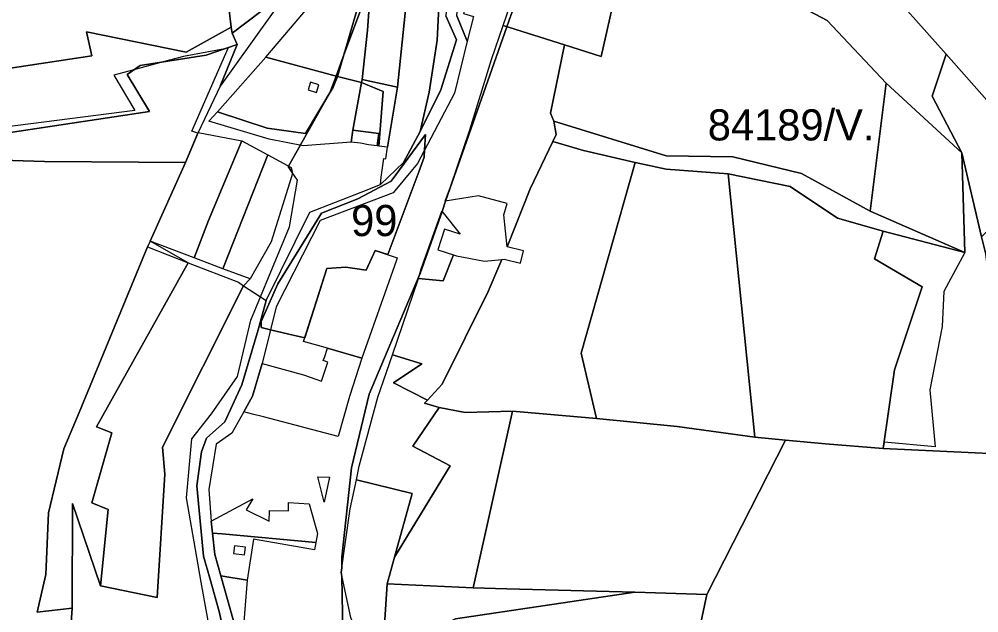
# Model space of a CAD drawing. Extents: x -477304 to -465429, y -1159113 to -1149210.
# Drawn here: x -475656.6 to -475194.4, y -1153026.8 to -1152741 of the extents above; entities that cross this region are included whole.
import ezdxf

# ---------------------------------------------------------------- set-up
doc = ezdxf.new("R2010")
doc.units = 0
for name, color, linetype in [('BPEJ_s', 7, 'Continuous'), ('orna_s', 7, 'Continuous'), ('PUPFL_s', 7, 'Continuous'), ('trav_porost_s', 7, 'Continuous'), ('voda_s', 7, 'Continuous'), ('zahrada_s', 7, 'Continuous')]:
    doc.layers.add(name, color=color, linetype=linetype)

msp = doc.modelspace()

# ---------------------------------------------------------------- linework, layer by layer
at = {"layer": 'BPEJ_s'}
for points in [[(-475500.81, -1153036.32), (-475501.16, -1153009.29), (-475501.54, -1153007.49), (-475501.21, -1153005.16), (-475501.28, -1153000), (-475496.5, -1152957), (-475488, -1152921.5), (-475464.1, -1152864.93), (-475463.5, -1152863.5), (-475452.96, -1152833.54), (-475451.22, -1152828.6), (-475421.69, -1152744.68), (-475407.14, -1152703.33)], [(-475407.14, -1152703.33), (-475421.69, -1152744.68), (-475451.22, -1152828.6), (-475452.96, -1152833.54), (-475463.5, -1152863.5), (-475464.1, -1152864.93), (-475488, -1152921.5), (-475496.5, -1152957), (-475501.28, -1153000), (-475501.21, -1153005.16)], [(-475489.77, -1152730.19), (-475500.69, -1152759.54), (-475504, -1152768.43), (-475507, -1152776.5), (-475507.3, -1152777.03), (-475521.24, -1152801.78), (-475526.88, -1152811.78), (-475527, -1152812), (-475525.07, -1152814.79), (-475524.91, -1152815.39), (-475535.25, -1152848.29), (-475545.44, -1152866.11), (-475548.51, -1152869.36), (-475587.54, -1152947.04), (-475586.48, -1152960.09), (-475590.2, -1153019.39), (-475617.49, -1153013.79), (-475613.73, -1152977.13), (-475621.62, -1152973.88), (-475611.96, -1152940.26), (-475619.33, -1152937.28), (-475575.21, -1152858.31), (-475593.59, -1152847.84), (-475576.52, -1152809.97), (-475570.52, -1152795.86), (-475573.5, -1152795), (-475556, -1152755), (-475557.53, -1152755.29), (-475577.5, -1152759), (-475587.33, -1152761.64), (-475601.43, -1152765.43), (-475611, -1152768), (-475601, -1152785), (-475688.7, -1152796.2)], [(-475563.53, -1153042.27), (-475569, -1153012), (-475571.07, -1153000), (-475576, -1152971.5), (-475573.5, -1152943), (-475564, -1152931), (-475551.5, -1152913), (-475545, -1152886), (-475540.37, -1152874.73), (-475526.5, -1152841), (-475522.5, -1152818.5), (-475525.07, -1152814.79), (-475527, -1152812), (-475526.88, -1152811.78), (-475521.24, -1152801.78), (-475507.3, -1152777.03), (-475507, -1152776.5), (-475504, -1152768.43), (-475500.69, -1152759.54), (-475489.77, -1152730.19)], [(-475279.36, -1152735.39), (-475267.5, -1152741.66), (-475238.97, -1152771.86), (-475202.55, -1152805.3), (-475201.18, -1152853.32), (-475211.2, -1152872.11), (-475212, -1152889), (-475218, -1152919.5), (-475215.5, -1152947), (-475240.05, -1152944.74), (-475240.48, -1152947.68), (-475268.28, -1152945.55), (-475287.45, -1152943.72), (-475325.37, -1153017.96), (-475330.61, -1153042.24)], [(-475279.36, -1152735.39), (-475267.5, -1152741.66), (-475238.97, -1152771.86), (-475202.55, -1152805.3), (-475201.18, -1152853.32), (-475211.2, -1152872.11), (-475212, -1152889), (-475218, -1152919.5), (-475215.5, -1152947), (-475240.05, -1152944.74), (-475240.48, -1152947.68), (-475268.28, -1152945.55), (-475287.45, -1152943.72), (-475325.37, -1153017.96), (-475330.61, -1153042.24)], [(-475524.91, -1152815.39), (-475535.25, -1152848.29), (-475545.44, -1152866.11), (-475548.51, -1152869.36), (-475587.54, -1152947.04), (-475586.48, -1152960.09), (-475590.2, -1153019.39), (-475617.49, -1153013.79), (-475613.73, -1152977.13), (-475621.62, -1152973.88), (-475611.96, -1152940.26), (-475619.33, -1152937.28), (-475575.21, -1152858.31), (-475593.59, -1152847.84), (-475576.52, -1152809.97), (-475570.52, -1152795.86), (-475573.5, -1152795), (-475556, -1152755), (-475557.53, -1152755.29), (-475577.5, -1152759), (-475587.33, -1152761.64), (-475601.43, -1152765.43), (-475611, -1152768), (-475601, -1152785), (-475688.7, -1152796.2)], [(-475563.53, -1153042.27), (-475569, -1153012), (-475571.07, -1153000), (-475576, -1152971.5), (-475573.5, -1152943), (-475564, -1152931), (-475551.5, -1152913), (-475545, -1152886), (-475540.37, -1152874.73), (-475526.5, -1152841), (-475522.5, -1152818.5), (-475525.07, -1152814.79), (-475524.91, -1152815.39)], [(-475501.21, -1153005.16), (-475501.54, -1153007.49), (-475501.16, -1153009.29), (-475500.81, -1153036.32)]]:
    msp.add_lwpolyline(points, dxfattribs=at)
for points in [[(-475464.14, -1152814.54), (-475479.09, -1152854.4), (-475485.14, -1152852.33), (-475489.52, -1152861.83), (-475499.35, -1152860.35), (-475508.44, -1152861.13), (-475519.11, -1152894.42), (-475526.82, -1152892.6), (-475535.6, -1152890.53), (-475540, -1152889.5), (-475540, -1152886.5), (-475532, -1152868.5), (-475511, -1152834.5), (-475493.5, -1152827.5), (-475477.5, -1152819), (-475461, -1152796.5), (-475461.34, -1152803.9), (-475461.5, -1152807.5), (-475462.83, -1152811.05)], [(-475464.14, -1152814.54), (-475462.83, -1152811.05), (-475461.5, -1152807.5), (-475461.34, -1152803.9), (-475461, -1152796.5), (-475477.5, -1152819), (-475493.5, -1152827.5), (-475511, -1152834.5), (-475532, -1152868.5), (-475540, -1152886.5), (-475540, -1152889.5), (-475535.6, -1152890.53), (-475526.82, -1152892.6), (-475519.11, -1152894.42), (-475508.44, -1152861.13), (-475499.35, -1152860.35), (-475489.52, -1152861.83), (-475485.14, -1152852.33), (-475479.09, -1152854.4)]]:
    msp.add_lwpolyline(points, close=True, dxfattribs=at)
at = {"layer": 'orna_s'}
for points in [[(-475474.41, -1152773.74), (-475470.29, -1152733.49), (-475466.26, -1152707.82), (-475459.33, -1152709.97), (-475453.25, -1152709.43), (-475455.35, -1152751.18), (-475459.14, -1152776.1), (-475463.5, -1152795.08), (-475471.52, -1152809.95), (-475482.63, -1152820.63), (-475482.23, -1152817.05), (-475481.05, -1152808.1), (-475480.01, -1152808.24), (-475479.28, -1152802.69)], [(-475492.49, -1152731.72), (-475503.36, -1152768.6), (-475537.87, -1152759.39), (-475508.67, -1152724.8), (-475503.55, -1152727.41)], [(-475488.91, -1152746.29), (-475487.74, -1152730.6), (-475483.62, -1152731.43), (-475470.29, -1152733.49), (-475474.41, -1152773.74), (-475491.45, -1152770.14)], [(-475537.87, -1152759.39), (-475503.36, -1152768.6), (-475505.33, -1152773.76), (-475518.78, -1152796.1), (-475537.26, -1152793.53), (-475561.15, -1152785.65)], [(-475516.28, -1152771.43), (-475517.38, -1152775.02), (-475513.35, -1152776.25), (-475512.25, -1152772.66)], [(-475593.59, -1152847.84), (-475576.52, -1152809.97), (-475570.41, -1152795.61), (-475549.31, -1152799.53), (-475565.52, -1152837.98), (-475572.32, -1152855.91)]]:
    msp.add_lwpolyline(points, close=True, dxfattribs=at)
at = {"layer": 'PUPFL_s'}
for points in [[(-475305.99, -1152727.63), (-475302.35, -1152706.82), (-475273.91, -1152717.63), (-475251.75, -1152720.8), (-475243.34, -1152720.48), (-475210.2, -1152757.89), (-475216.87, -1152778.07), (-475202.55, -1152805.3), (-475238.97, -1152771.86), (-475267.5, -1152741.66), (-475279.36, -1152735.39)], [(-475688.75, -1152784.73), (-475693.19, -1152770.91), (-475686.56, -1152768.49), (-475621.57, -1152758.65), (-475624.23, -1152747.16), (-475576.16, -1152756.87), (-475554.46, -1152744.91), (-475554.12, -1152747.68), (-475551.6, -1152753.22), (-475566.51, -1152758.41), (-475598.28, -1152763.34), (-475604.67, -1152767.58), (-475593.82, -1152785.42), (-475688.69, -1152799.79)], [(-475694.55, -1152800.67), (-475688.69, -1152799.79), (-475593.82, -1152785.42), (-475604.67, -1152767.58), (-475598.28, -1152763.34), (-475566.51, -1152758.41), (-475551.6, -1152753.22), (-475559.87, -1152773.35), (-475570.41, -1152795.61), (-475576.52, -1152809.97), (-475644.5, -1152809.53), (-475700.83, -1152807.76), (-475694.32, -1152806.09)], [(-475193.07, -1152845.82), (-475202.55, -1152805.3), (-475216.87, -1152778.07), (-475210.2, -1152757.89), (-475161.18, -1152813.24)], [(-475240.42, -1152843.05), (-475201.18, -1152853.32), (-475202.55, -1152805.3), (-475193.07, -1152845.82), (-475190.97, -1152854.13), (-475184.7, -1152902.6), (-475185.82, -1152950.28), (-475240.48, -1152947.68), (-475234.99, -1152909.87), (-475221.7, -1152869.94), (-475244.73, -1152856.39)], [(-475154.57, -1152960.71), (-475188.25, -1153073.92), (-475205.9, -1153072.04), (-475319.2, -1153107.9), (-475350.51, -1153121.3), (-475347.24, -1153109.36), (-475336.52, -1153070.18), (-475330.61, -1153042.24), (-475325.37, -1153017.96), (-475287.45, -1152943.72), (-475268.28, -1152945.55), (-475240.48, -1152947.68), (-475185.82, -1152950.28), (-475184.7, -1152902.6), (-475190.97, -1152854.13), (-475193.07, -1152845.82), (-475161.18, -1152813.24), (-475126.45, -1152850.38), (-475138.02, -1152881.46), (-475143.48, -1152923), (-475153.28, -1152956.92)], [(-475575.21, -1152858.31), (-475619.33, -1152937.28), (-475611.96, -1152940.26), (-475621.62, -1152973.88), (-475613.73, -1152977.13), (-475617.49, -1153013.79), (-475630.92, -1152974.27), (-475631.11, -1153024.55), (-475648.02, -1153026.57), (-475643.82, -1153008.41), (-475642.55, -1152978.65), (-475635.17, -1152947.89), (-475627.73, -1152930.46), (-475594.83, -1152850.7)]]:
    msp.add_lwpolyline(points, close=True, dxfattribs=at)
for points in [[(-475161.18, -1152813.24), (-475210.2, -1152757.89), (-475243.34, -1152720.48)], [(-475700.83, -1152807.76), (-475644.5, -1152809.53), (-475576.52, -1152809.97), (-475593.59, -1152847.84), (-475594.83, -1152850.7), (-475627.73, -1152930.46), (-475635.17, -1152947.89), (-475642.55, -1152978.65), (-475643.82, -1153008.41), (-475648.02, -1153026.57), (-475631.11, -1153024.55), (-475635.36, -1153085.02), (-475662.21, -1153095.67)], [(-475635.36, -1153085.02), (-475631.11, -1153024.55), (-475630.92, -1152974.27), (-475617.49, -1153013.79), (-475590.2, -1153019.39), (-475586.48, -1152960.09), (-475587.54, -1152947.04), (-475548.51, -1152869.36), (-475537.64, -1152876.53), (-475541.47, -1152890.66), (-475549.36, -1152917.02), (-475557.61, -1152934.96), (-475566.47, -1152942.81), (-475568.81, -1152949.28), (-475571.1, -1152965.73), (-475567.92, -1152999.53), (-475564.76, -1153010.23), (-475560.24, -1153026.23), (-475557.79, -1153037.72)]]:
    msp.add_lwpolyline(points, dxfattribs=at)
at = {"layer": 'trav_porost_s'}
for points in [[(-475556.79, -1152726.11), (-475563.59, -1152714.27), (-475568.62, -1152709.29), (-475579.41, -1152701.49), (-475574.39, -1152690.12), (-475561.12, -1152693.94), (-475549.78, -1152702.51), (-475547.62, -1152704.31), (-475539.13, -1152723.9), (-475540.16, -1152737.25), (-475554.12, -1152747.68), (-475554.46, -1152744.91)], [(-475563.59, -1152714.27), (-475556.79, -1152726.11), (-475554.46, -1152744.91), (-475576.16, -1152756.87), (-475624.23, -1152747.16), (-475621.57, -1152758.65), (-475686.56, -1152768.49), (-475695.79, -1152741.11), (-475675.66, -1152712.58), (-475642.36, -1152708.05), (-475639.99, -1152696.96), (-475614.53, -1152691.15), (-475585.75, -1152697.58), (-475579.41, -1152701.49), (-475568.62, -1152709.29)], [(-475554.12, -1152747.68), (-475540.16, -1152737.25), (-475539.13, -1152723.9), (-475547.62, -1152704.31), (-475549.78, -1152702.51), (-475525.94, -1152703.82), (-475516.8, -1152709.11), (-475516.03, -1152717.12), (-475528.22, -1152728.96), (-475559.87, -1152773.35), (-475551.6, -1152753.22)], [(-475393.95, -1152753.43), (-475423.54, -1152744.1), (-475412.15, -1152710.92), (-475408.98, -1152702.9), (-475391.14, -1152707.11), (-475386.32, -1152711.18), (-475378.53, -1152710.47), (-475366.01, -1152713.43), (-475376.34, -1152758.98)], [(-475451.16, -1152739.41), (-475446.01, -1152751.01), (-475453.49, -1152775), (-475463.5, -1152795.08), (-475459.14, -1152776.1), (-475455.35, -1152751.18), (-475453.25, -1152709.43), (-475449.1, -1152710.68)], [(-475279.36, -1152735.39), (-475267.5, -1152741.66), (-475238.97, -1152771.86), (-475246.77, -1152833.38), (-475279.83, -1152815.27), (-475312.9, -1152807.3), (-475344.92, -1152806.82), (-475399.13, -1152790.1), (-475400.75, -1152786.24), (-475393.95, -1152753.43), (-475376.34, -1152758.98), (-475366.01, -1152713.43), (-475311.18, -1152726.4), (-475305.99, -1152727.63)], [(-475492.49, -1152731.72), (-475503.55, -1152727.41), (-475487.74, -1152730.6), (-475488.91, -1152746.29), (-475491.45, -1152770.14), (-475491.69, -1152771.47), (-475503.36, -1152768.6)], [(-475400.75, -1152786.24), (-475399.13, -1152790.1), (-475397.98, -1152796.54), (-475399.54, -1152799.89), (-475410.48, -1152822.74), (-475421.55, -1152850.68), (-475423.16, -1152835.29), (-475421.65, -1152829.81), (-475435.38, -1152826.04), (-475451.39, -1152828.63), (-475448.91, -1152821.68), (-475439.62, -1152794.25), (-475429.17, -1152760.48), (-475423.54, -1152744.1), (-475393.95, -1152753.43)], [(-475519.91, -1152802.05), (-475536.3, -1152798.75), (-475565.28, -1152790.1), (-475561.15, -1152785.65), (-475537.26, -1152793.53), (-475518.78, -1152796.1), (-475505.33, -1152773.76), (-475503.36, -1152768.6), (-475491.69, -1152771.47), (-475495.93, -1152794.52), (-475496.67, -1152800.17)], [(-475495.93, -1152794.52), (-475491.69, -1152771.47), (-475481.32, -1152775.88), (-475483.43, -1152802.15), (-475484.25, -1152802.04), (-475483.45, -1152795.99)], [(-475491.45, -1152770.14), (-475474.41, -1152773.74), (-475479.28, -1152802.69), (-475483.43, -1152802.15), (-475481.32, -1152775.88), (-475491.69, -1152771.47)], [(-475238.97, -1152771.86), (-475202.55, -1152805.3), (-475201.18, -1152853.32), (-475246.77, -1152833.38)], [(-475384.78, -1152804.32), (-475399.54, -1152799.89), (-475397.98, -1152796.54), (-475399.13, -1152790.1), (-475344.92, -1152806.82), (-475312.9, -1152807.3), (-475279.83, -1152815.27), (-475246.77, -1152833.38), (-475201.18, -1152853.32), (-475240.42, -1152843.05), (-475262.43, -1152836.75), (-475285.2, -1152821.61), (-475315.16, -1152815.54), (-475345, -1152813.24), (-475359.94, -1152810)], [(-475484.25, -1152802.04), (-475488.39, -1152801.5), (-475492.21, -1152800.76), (-475496.67, -1152800.17), (-475495.93, -1152794.52), (-475483.45, -1152795.99)], [(-475558.47, -1152861.17), (-475572.32, -1152855.91), (-475565.52, -1152837.98), (-475549.31, -1152799.53), (-475536.93, -1152806.29)], [(-475460.02, -1152924.47), (-475452.88, -1152916.76), (-475430.76, -1152872.18), (-475424.14, -1152856.73), (-475422.97, -1152856.61), (-475415.09, -1152858.5), (-475413.67, -1152852.57), (-475421.55, -1152850.68), (-475410.48, -1152822.74), (-475399.54, -1152799.89), (-475384.78, -1152804.32), (-475359.94, -1152810), (-475385.91, -1152901.78), (-475378.54, -1152933.24), (-475418.96, -1152929.67), (-475441.84, -1152930.38), (-475454.37, -1152927.96), (-475461.39, -1152925.95)], [(-475525.7, -1152812.42), (-475524.91, -1152815.39), (-475535.25, -1152848.29), (-475545.44, -1152866.11), (-475558.47, -1152861.17), (-475536.93, -1152806.29)], [(-475385.91, -1152901.78), (-475359.94, -1152810), (-475345, -1152813.24), (-475315.16, -1152815.54), (-475302.24, -1152942.31), (-475339.72, -1152937.13), (-475378.54, -1152933.24)], [(-475268.28, -1152945.55), (-475287.45, -1152943.72), (-475302.24, -1152942.31), (-475315.16, -1152815.54), (-475285.2, -1152821.61), (-475262.43, -1152836.75), (-475240.42, -1152843.05), (-475244.73, -1152856.39), (-475221.7, -1152869.94), (-475234.99, -1152909.87), (-475240.48, -1152947.68)], [(-475485.14, -1152852.33), (-475474.51, -1152855.97), (-475474.88, -1152857.07), (-475491.51, -1152904.28), (-475508.15, -1152899.46), (-475519.66, -1152896.13), (-475508.44, -1152861.13), (-475499.35, -1152860.35), (-475489.52, -1152861.83)], [(-475548.51, -1152869.36), (-475587.54, -1152947.04), (-475586.48, -1152960.09), (-475590.2, -1153019.39), (-475617.49, -1153013.79), (-475613.73, -1152977.13), (-475621.62, -1152973.88), (-475611.96, -1152940.26), (-475619.33, -1152937.28), (-475575.21, -1152858.31), (-475551.06, -1152867.68)], [(-475483.8, -1152923.03), (-475476.85, -1152902.59), (-475462.75, -1152906.9), (-475476.32, -1152916.03), (-475460.02, -1152924.47), (-475461.39, -1152925.95), (-475454.37, -1152927.96), (-475467.1, -1152946.61), (-475449.11, -1152956.13), (-475475.8, -1153000), (-475467.4, -1152969.33), (-475494.22, -1152962.84), (-475492.8, -1152956.23)], [(-475449.11, -1152956.13), (-475467.1, -1152946.61), (-475454.37, -1152927.96), (-475441.84, -1152930.38), (-475418.96, -1152929.67), (-475437.91, -1153014.81), (-475479.39, -1153012.83), (-475475.8, -1153000)], [(-475302.24, -1152942.31), (-475287.45, -1152943.72), (-475325.37, -1153017.96), (-475360.14, -1153016.97), (-475421.68, -1153015.23), (-475437.91, -1153014.81), (-475418.96, -1152929.67), (-475378.54, -1152933.24), (-475339.72, -1152937.13)], [(-475512.75, -1152961.31), (-475507.18, -1152961.51), (-475509.71, -1152973.57)], [(-475494.22, -1152962.84), (-475467.4, -1152969.33), (-475475.8, -1153000), (-475479.39, -1153012.83), (-475481.6, -1153047.42), (-475463.12, -1153092.06), (-475466.61, -1153093.16), (-475472.52, -1153095.04), (-475496.95, -1153029.07), (-475501.54, -1153007.49), (-475497.2, -1152976.78)], [(-475526.88, -1152973.78), (-475516.91, -1152974.32), (-475512.88, -1152988.66), (-475513.77, -1152992.91), (-475558.81, -1152988.85), (-475563.49, -1152988.42), (-475564.12, -1152982.64), (-475544.04, -1152971.94), (-475547.34, -1152977.21), (-475536.23, -1152982.69), (-475536.06, -1152977.6), (-475526.96, -1152977.78)], [(-475563.49, -1152988.42), (-475558.81, -1152988.85), (-475513.77, -1152992.91), (-475514.34, -1152996.46), (-475543.84, -1152991.36), (-475546.78, -1153011.14), (-475559.5, -1153009.05), (-475562.37, -1152998.73)], [(-475553.36, -1152998.26), (-475548.15, -1152998.9), (-475547.7, -1152995.24), (-475552.92, -1152994.58)], [(-475559.5, -1153009.05), (-475546.78, -1153011.14), (-475548.45, -1153031.15), (-475553.48, -1153030.67)], [(-475437.91, -1153014.81), (-475421.68, -1153015.23), (-475360.14, -1153016.97), (-475446.53, -1153029.81), (-475481.6, -1153047.42), (-475479.39, -1153012.83)], [(-475463.12, -1153092.06), (-475481.6, -1153047.42), (-475446.53, -1153029.81), (-475360.14, -1153016.97), (-475325.37, -1153017.96), (-475330.61, -1153042.24), (-475336.52, -1153070.18), (-475462.34, -1153123.43), (-475461.63, -1153108.89), (-475461.12, -1153095.55)]]:
    msp.add_lwpolyline(points, close=True, dxfattribs=at)
at = {"layer": 'voda_s'}
for points in [[(-475557.79, -1153037.72), (-475560.24, -1153026.23), (-475564.76, -1153010.23), (-475567.92, -1152999.53), (-475571.1, -1152965.73), (-475568.81, -1152949.28), (-475566.47, -1152942.81), (-475557.61, -1152934.96), (-475549.36, -1152917.02), (-475541.47, -1152890.66), (-475537.64, -1152876.53), (-475516.59, -1152833.94), (-475491.87, -1152824.25), (-475482.63, -1152820.63), (-475471.52, -1152809.95), (-475463.5, -1152795.08), (-475453.49, -1152775), (-475446.01, -1152751.01), (-475451.16, -1152739.41)], [(-475445.76, -1152739.47), (-475440.93, -1152751.63), (-475447.03, -1152776.68), (-475464.82, -1152810.53), (-475467.24, -1152813.44), (-475476.52, -1152824.58), (-475511.67, -1152838.03), (-475532.87, -1152879.56), (-475535.95, -1152891.92), (-475539.67, -1152906.85), (-475544.24, -1152922.49), (-475548.43, -1152930.05), (-475554.15, -1152940.37), (-475561.8, -1152945.58), (-475565.3, -1152967.49), (-475564.12, -1152982.64), (-475563.49, -1152988.42), (-475562.37, -1152998.73), (-475559.5, -1153009.05), (-475553.48, -1153030.67)]]:
    msp.add_lwpolyline(points, dxfattribs=at)
at = {"layer": 'zahrada_s'}
for points in [[(-475439.25, -1152725.01), (-475442.55, -1152738.35), (-475437.73, -1152739.75), (-475440.93, -1152751.63), (-475445.76, -1152739.47), (-475443.64, -1152712.13), (-475438.91, -1152714.97)], [(-475464.37, -1152865.85), (-475463.02, -1152861.18), (-475453.09, -1152833.38), (-475444.2, -1152844.51), (-475451.82, -1152842.06), (-475455.03, -1152852.06), (-475447.4, -1152854.49), (-475452.4, -1152867.04)], [(-475430.76, -1152872.18), (-475452.88, -1152916.76), (-475460.02, -1152924.47), (-475476.32, -1152916.03), (-475462.75, -1152906.9), (-475476.85, -1152902.59), (-475464.37, -1152865.85), (-475452.4, -1152867.04), (-475447.4, -1152854.49), (-475446.06, -1152854.94), (-475432.48, -1152857.55), (-475424.14, -1152856.73)], [(-475538.99, -1152932.46), (-475544.24, -1152931.13), (-475548.43, -1152930.05), (-475544.24, -1152922.49), (-475539.67, -1152906.85), (-475519.75, -1152912.32), (-475511.03, -1152915.25), (-475507.97, -1152906.15), (-475510.15, -1152905.42), (-475509.64, -1152903.9), (-475508.15, -1152899.46), (-475491.51, -1152904.28), (-475497.54, -1152922.65), (-475503.01, -1152941.9)]]:
    msp.add_lwpolyline(points, close=True, dxfattribs=at)

# ---------------------------------------------------------------- texts
at = {"layer": 'BPEJ_s'}
for s, p in [('84189/V.', (-475324.96, -1152799.41)), ('99', (-475496.75, -1152845.46))]:
    msp.add_text(s, height=15, dxfattribs=at).set_placement(p)

doc.saveas('drawing.dxf')
